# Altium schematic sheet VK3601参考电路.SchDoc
size A4
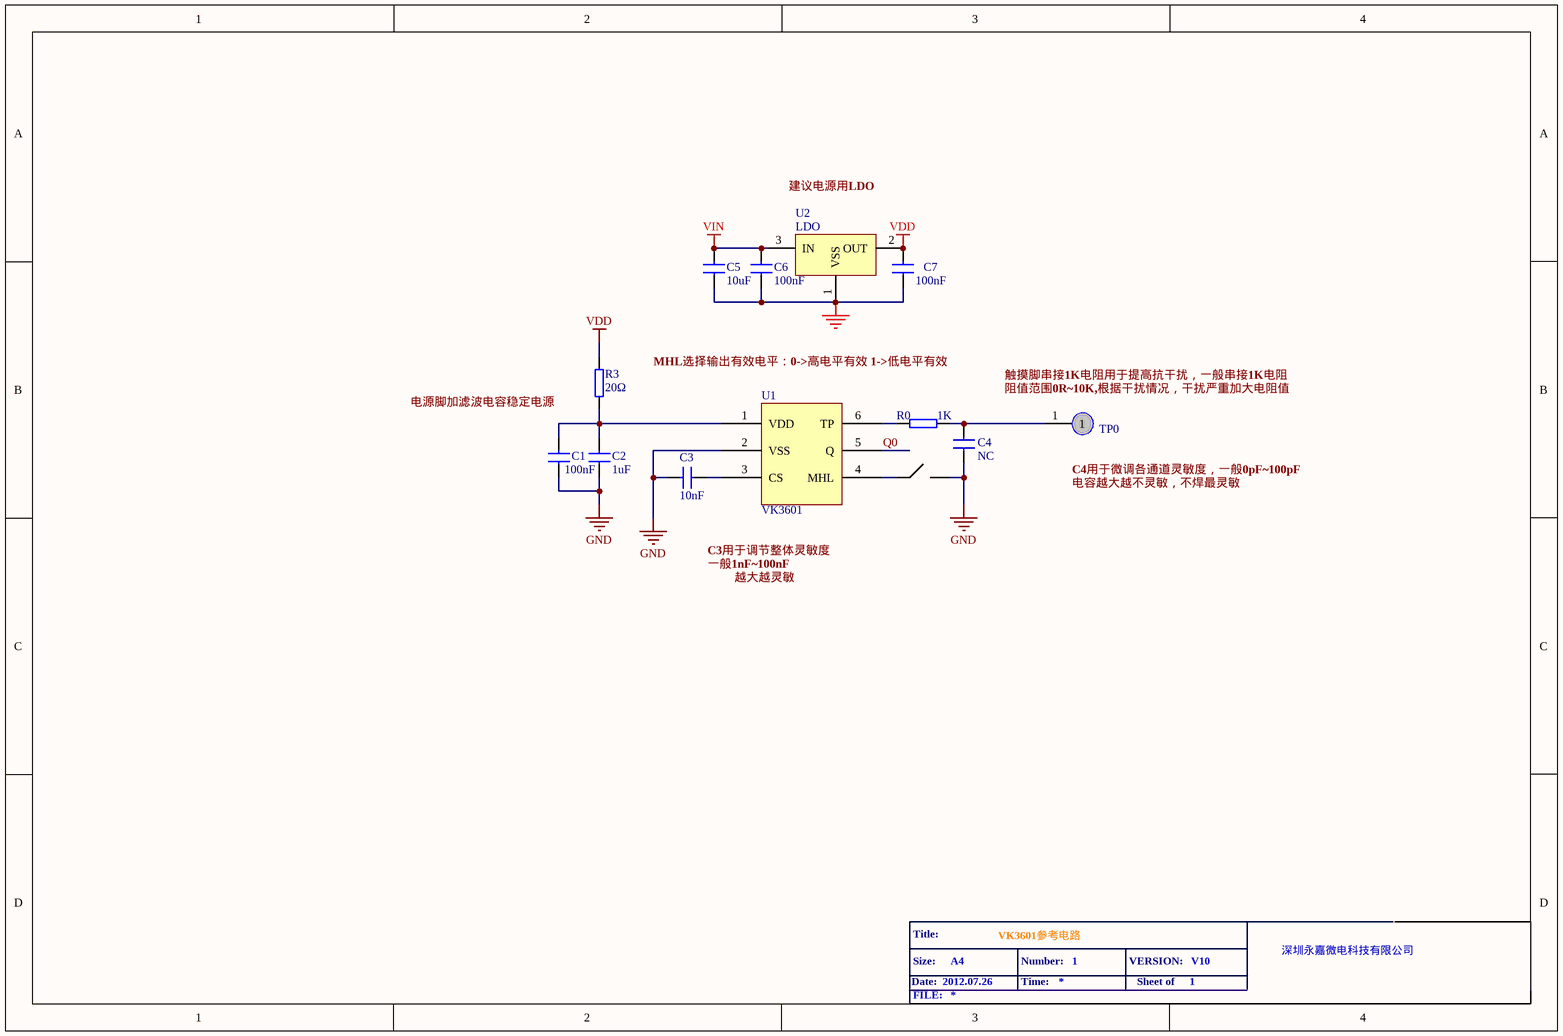
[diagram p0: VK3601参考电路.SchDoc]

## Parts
C1  100nF  [0603-C]
C2  value 1uF  [0603-C]  (hidden comment: 10uF)
C3  value 10nF  [0603-C]  (hidden comment: 10uF)
C4  value NC  [0603-C]  (hidden comment: 10uF)
C5  10uF  [0805-C]
C6  100nF  [0805-C]
C7  100nF  [0805-C]
key1  开关  (value not drawn)
R0  1K  [0603-R]
R3  20Ω  [0603-R]
TP0  TPAD  [TP-PAD0]  (value not drawn)
U1  VK3601
U2  LDO  [SOT-23]

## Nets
GND: C1.2 C2.2 C3.2 C4.1 C5.2 C6.2 C7.2 U1.2(VSS) U2.1(VSS)
VDD: C7.1 R3.1 U2.2(OUT)
VIN: C5.1 C6.1 U2.3(IN)
Q0: U1.5(Q)
NetC1_1: C1.1 C2.1 R3.2 U1.1(VDD)
NetC3_1: C3.1 U1.3(CS)
NetC4_2: C4.2 R0.1 TP0.1
NetR0_2: R0.2 U1.6(TP)

Not connected (* = marked no-connect by the designer): U1 4(MHL)

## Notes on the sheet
- 建议电源用LDO
- MHL选择输出有效电平：0->高电平有效 1->低电平有效
- (near TP0) 触摸脚串接1K电阻用于提高抗干扰，一般串接1K电阻
- 电源脚加滤波电容稳定电源
- (near TP0) 阻值范围0R
  0K,根据干扰情况，干扰严重加大电阻值
- (near TP0) C4用于微调各通道灵敏度，一般0pF
  00pF
- 电容越大越不灵敏，不焊最灵敏
- C3用于调节整体灵敏度
- 一般1nF
  00nF
- 越大越灵敏
- Date:
- Title:
- Size:
- 2012.07.26
- A4
- VK3601参考电路
- Number:
- Time:
- 1
- VERSION:
- Sheet of
- V10
- 深圳永嘉微电科技有限公司
- FILE:

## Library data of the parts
C1-C7 = CAP: Capacitor
key1 = 单刀单掷开关
R0 R3 = RES: Resistor
TP0 = TPAD: TESTING
U1 = VK3601 SOT23-6
U2 = V6206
